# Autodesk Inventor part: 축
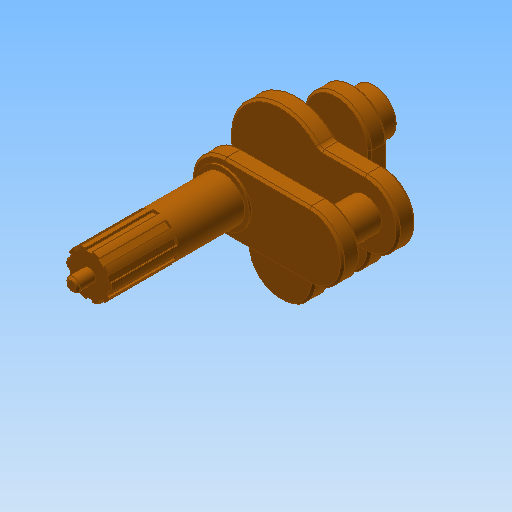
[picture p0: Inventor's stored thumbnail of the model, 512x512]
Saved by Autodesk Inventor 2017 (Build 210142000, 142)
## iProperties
Created: 2017-05
Part Number: 축
Material: 강철, 연강
Document SubType Name: Modeling
Designer: mduedu
Density: 7.86 g/cm^3
Mass: 656.198 g
Surface Area: 242.498 cm^2
Volume: 83.4857 cm^3
Appearance: 주황색
Author: mduedu
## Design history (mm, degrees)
sketch "스케치1"
  geometry: L1 (-38, 15)-(-17.436, 15); L2 (-38, -15)-(-17.436, -15); L3 (-15, -38)-(-15, -17.436); L4 (15, -38)-(15, -17.436); A1 r 23 centre (0, 0) between (-17.436, 15) and (-17.436, -15); A2 r 15 centre (-38, 0) between (-38, 15) and (-38, -15); A3 r 15 centre (0, -38) between (-15, -38) and (15, -38); 1 further point
  constraints: 8 end point, 8 point on circle, 4 tangent, 3 centre point, 2 horizontal, 2 vertical, 1 coincident, 1 horizontal alignment, 1 vertical alignment
  dimensions: "d0" = 46 diameter of A1; "d1" = 30 diameter of A2; "d2" = 30 diameter of A3 (= d1); "d3" = 38 distance of point (0, 0) A2.centre; "d4" = 38 distance of A3.centre point (0, 0)
extrude "돌출1" new body sketch "스케치1" distance "d5" = 8; taper "d6" = 0 deg
fillet "모깎기1" dims "d7" = 3
sketch "스케치2"
  geometry: C1 r 7.5 at (0, -38); A1 r 15 centre (0, -38) between (-15, -38) and (15, -38) reference; 1 further point
  constraints: 1 centre point, 1 coincident
  dimensions: "d8" = 15 diameter of C1
extrude "돌출2" join sketch "스케치2" distance "d9" = 17; taper "d10" = 0 deg
sketch "스케치3"
  geometry: L1 (-15, 0)-(-15, 38); L2 (15, 0)-(15, 38); C1 r 7.5 at (0, 0) reference; A1 r 15 centre (0, 0) between (-15, 0) and (15, 0); A2 r 15 centre (0, 38) between (-15, 38) and (15, 38); 1 further point
  constraints: 4 end point, 4 point on circle, 4 tangent, 2 centre point, 2 coincident
  dimensions: "d11" = 30 diameter of A1; "d12" = 30 diameter of A2 (= d11)
extrude "돌출3" join sketch "스케치3" distance "d13" = 8; taper "d14" = 0 deg
sketch "스케치4"
  geometry: C1 r 12 at (0, 38); A1 r 15 centre (0, 38) between (15, 38) and (-15, 38) reference; 1 further point
  constraints: 1 centre point, 1 coincident
  dimensions: "d15" = 24 diameter of C1
extrude "돌출4" join sketch "스케치4" distance "d16" = 1; taper "d17" = 0 deg
sketch "스케치5"
  geometry: C1 r 10 at (0, 0); 1 further point
  constraints: 1 centre point, 1 coincident
  dimensions: "d18" = 20 diameter of C1
extrude "돌출5" join sketch "스케치5" distance "d19" = 8; taper "d20" = 0 deg
sketch "스케치6"
  geometry: C1 r 7.5 at (38, 0); A1 r 15 centre (38, 0) between (38, -15) and (38, 15) reference; 1 further point
  constraints: 1 centre point, 1 coincident
  dimensions: "d21" = 15 diameter of C1
extrude "돌출6" join sketch "스케치6" distance "d22" = 17; taper "d23" = 0 deg
sketch "스케치7"
  geometry: L1 (-38, 15)-(0, 15); L2 (-38, -15)-(0, -15); C1 r 7.5 at (0, 0) reference; A1 r 15 centre (0, 0) between (0, 15) and (0, -15); A2 r 15 centre (-38, 0) between (-38, 15) and (-38, -15); 1 further point
  constraints: 4 end point, 4 point on circle, 4 tangent, 2 centre point, 2 coincident
  dimensions: "d24" = 30 diameter of A1; "d25" = 30 diameter of A2 (= d24)
extrude "돌출7" join sketch "스케치7" distance "d26" = 8; taper "d27" = 0 deg
sketch "스케치8"
  geometry: C1 r 12 at (-38, 0); 1 further point
  constraints: 1 centre point, 1 coincident
  dimensions: "d28" = 24 diameter of C1
extrude "돌출8" join sketch "스케치8" distance "d29" = 1; taper "d30" = 0 deg
sketch "스케치9"
  geometry: C1 r 10 at (0, 0); 1 further point
  constraints: 1 centre point, 1 coincident
  dimensions: "d31" = 20 diameter of C1
extrude "돌출9" join sketch "스케치9" distance "d32" = 30; taper "d33" = 0 deg
sketch "스케치10"
  geometry: L1 (1.5, 9.887)-(1.5, 8.887); L2 (1.5, 8.887)-(-1.5, 8.887); L3 (-1.5, 8.887)-(-1.5, 9.887); L4 (-4.598, 8.88)-(-4.01, 8.071); L5 (-4.01, 8.071)-(-6.437, 6.308); L6 (-6.437, 6.308)-(-7.025, 7.117); L7 (-8.939, 4.482)-(-7.988, 4.173); L8 (-7.988, 4.173)-(-8.915, 1.32); L9 (-8.915, 1.32)-(-9.866, 1.629); L10 (-9.866, -1.629)-(-8.915, -1.32); L11 (-8.915, -1.32)-(-7.988, -4.173); L12 (-7.988, -4.173)-(-8.939, -4.482); L13 (-7.025, -7.117)-(-6.437, -6.308); L14 (-6.437, -6.308)-(-4.01, -8.071); L15 (-4.01, -8.071)-(-4.598, -8.88); L16 (-1.5, -9.887)-(-1.5, -8.887); L17 (-1.5, -8.887)-(1.5, -8.887); L18 (1.5, -8.887)-(1.5, -9.887); L19 (4.598, -8.88)-(4.01, -8.071); L20 (4.01, -8.071)-(6.437, -6.308); L21 (6.437, -6.308)-(7.025, -7.117); L22 (8.939, -4.482)-(7.988, -4.173); L23 (7.988, -4.173)-(8.915, -1.32); L24 (8.915, -1.32)-(9.866, -1.629); L25 (9.866, 1.629)-(8.915, 1.32); L26 (8.915, 1.32)-(7.988, 4.173); L27 (7.988, 4.173)-(8.939, 4.482); L28 (7.025, 7.117)-(6.437, 6.308); L29 (6.437, 6.308)-(4.01, 8.071); L30 (4.01, 8.071)-(4.598, 8.88); A1 r 10 centre (0, 0) between (1.5, 9.887) and (-1.5, 9.887); A2 r 10 centre (0, 0) between (-4.598, 8.88) and (-7.025, 7.117); A3 r 10 centre (0, 0) between (-8.939, 4.482) and (-9.866, 1.629); A4 r 10 centre (0, 0) between (-9.866, -1.629) and (-8.939, -4.482); A5 r 10 centre (0, 0) between (-7.025, -7.117) and (-4.598, -8.88); A6 r 10 centre (0, 0) between (-1.5, -9.887) and (1.5, -9.887); A7 r 10 centre (0, 0) between (4.598, -8.88) and (7.025, -7.117); A8 r 10 centre (0, 0) between (8.939, -4.482) and (9.866, -1.629); A9 r 10 centre (0, 0) between (9.866, 1.629) and (8.939, 4.482); A10 r 10 centre (0, 0) between (7.025, 7.117) and (4.598, 8.88); 13 further points
  constraints: 60 end point, 20 point on circle, 10 centre point, 3 coincident, 1 horizontal, 1 midpoint, 1 parallel, 1 vertical, 1 vertical alignment, 103 other
  dimensions: "d37" = 3 distance of L1.end L2.end; "d39" = 1 distance of L2.end L3.end; "d42" = 360 deg dimension on A1.centre L1.start (derived)
extrude "돌출10" join sketch "스케치10" distance "d44" = 30; taper "d45" = 0 deg
sketch "스케치11"
  geometry: C1 r 3 at (0, 0); 1 further point
  constraints: 1 centre point, 1 coincident
  dimensions: "d49" = 6 diameter of C1
extrude "돌출11" join sketch "스케치11" distance "d50" = 8; taper "d51" = 0 deg
chamfer "모따기1" distance "d46" = 1; stored, may be unused: second distance "d47" = 2, angle "d48" = 45 deg
node "솔리드1"
node "투영된 루프1"
node "투영된 루프2"
node "투영된 루프3"
